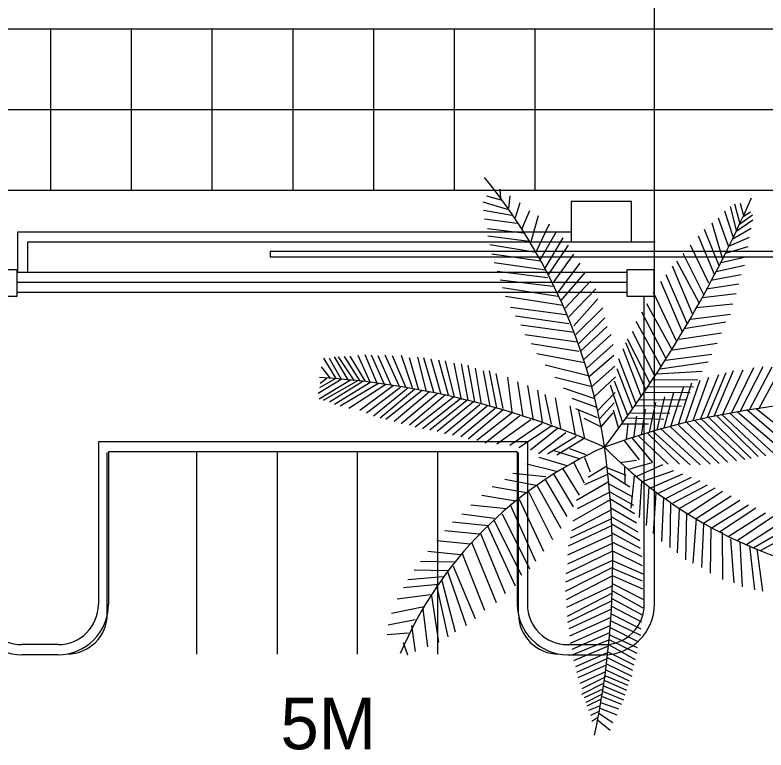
# Model space of a CAD drawing. Extents: x 6711323 to 6714641, y 1869258 to 1871224.
# Drawn here: x 6712869.21 to 6712906.43, y 1869705.35 to 1869741.77 of the extents above; entities that cross this region are included whole.
import ezdxf

# ---------------------------------------------------------------- set-up
doc = ezdxf.new("R2010")
doc.units = 0
for name, color, linetype in [('Curb Gutter (21)', 7, 'Continuous'), ('Exist Veg_Nat(4)', 7, 'Continuous'), ('Front Align (17)', 7, 'Continuous'), ('Misc CnstDet(22)', 7, 'Continuous'), ('Pave Edges (20)', 7, 'Continuous'), ('Ramp Anno (14)', 7, 'Continuous'), ('Undefined (Lv19)', 7, 'Continuous'), ('Undefined (Lv26)', 7, 'Continuous')]:
    doc.layers.add(name, color=color, linetype=linetype)

msp = doc.modelspace()

# ---------------------------------------------------------------- linework, layer by layer
at = {"layer": 'Curb Gutter (21)'}
for p, q in [((6712900.899, 1869712.572), (6712900.899, 1869761.572)), ((6712900.399, 1869712.572), (6712900.399, 1869727.849)), ((6712873.344, 1869720.618), (6712873.344, 1869712.572)), ((6712894.607, 1869720.618), (6712873.344, 1869720.618)), ((6712894.607, 1869720.618), (6712894.607, 1869712.572)), ((6712873.786, 1869712.099), (6712873.786, 1869720.099)), ((6712894.107, 1869720.118), (6712873.844, 1869720.118)), ((6712873.844, 1869720.118), (6712873.844, 1869712.572)), ((6712894.107, 1869720.118), (6712894.107, 1869712.572)), ((6712894.164, 1869712.099), (6712894.164, 1869720.099)), ((6712871.344, 1869710.572), (6712869.552, 1869710.572)), ((6712896.607, 1869710.572), (6712898.399, 1869710.572)), ((6712871.344, 1869710.072), (6712869.552, 1869710.072)), ((6712896.607, 1869710.072), (6712898.399, 1869710.072))]:
    msp.add_line(p, q, dxfattribs=at)
for centre, radius, start, end in [((6712869.552, 1869712.572), 2.5, 180, 270), ((6712869.552, 1869712.572), 2, 180, 270), ((6712871.344, 1869712.572), 2.5, 270, 0), ((6712871.344, 1869712.572), 2, 270, 0), ((6712896.607, 1869712.572), 2.5, 180, 270), ((6712896.607, 1869712.572), 2, 180, 270), ((6712898.399, 1869712.572), 2.5, 270, 360), ((6712898.399, 1869712.572), 2, 270, 360), ((6712871.786, 1869712.099), 2, 270, 0), ((6712896.164, 1869712.099), 2, 180, 270)]:
    msp.add_arc(centre, radius, start, end, dxfattribs=at)
at = {"layer": 'Exist Veg_Nat(4)'}
for p, q in [((6712893.287, 1869732.658), (6712893.263, 1869733.147)), ((6712893.371, 1869732.585), (6712892.598, 1869732.803)), ((6712893.689, 1869732.199), (6712893.753, 1869732.818)), ((6712893.624, 1869732.144), (6712892.418, 1869732.499)), ((6712894.017, 1869731.748), (6712894.244, 1869732.489)), ((6712905.139, 1869731.476), (6712904.89, 1869732.406)), ((6712905.319, 1869731.878), (6712905.165, 1869732.436)), ((6712893.841, 1869731.844), (6712892.424, 1869732.083)), ((6712894.331, 1869731.159), (6712894.727, 1869732.092)), ((6712904.803, 1869730.774), (6712904.391, 1869732.047)), ((6712904.977, 1869731.109), (6712904.665, 1869732.287)), ((6712905.295, 1869731.795), (6712905.659, 1869732.027)), ((6712894.099, 1869731.449), (6712892.48, 1869731.662)), ((6712894.793, 1869730.556), (6712895.151, 1869731.839)), ((6712904.59, 1869730.271), (6712904.084, 1869731.714)), ((6712905.119, 1869731.417), (6712905.76, 1869731.874)), ((6712895.04, 1869730.043), (6712895.708, 1869731.434)), ((6712904.277, 1869729.728), (6712903.763, 1869731.453)), ((6712904.942, 1869731.039), (6712905.774, 1869731.629)), ((6712894.396, 1869730.957), (6712892.63, 1869731.185)), ((6712895.219, 1869729.608), (6712896.043, 1869731.052)), ((6712904.103, 1869729.34), (6712903.388, 1869731.149)), ((6712904.763, 1869730.659), (6712905.694, 1869731.209)), ((6712894.702, 1869730.556), (6712892.641, 1869730.815)), ((6712895.48, 1869729.233), (6712896.385, 1869730.738)), ((6712903.877, 1869728.908), (6712903.081, 1869730.817)), ((6712904.597, 1869730.318), (6712905.608, 1869730.768)), ((6712895.044, 1869730.013), (6712892.746, 1869730.389)), ((6712895.674, 1869728.935), (6712896.646, 1869730.364)), ((6712903.603, 1869728.48), (6712902.686, 1869730.373)), ((6712904.43, 1869729.976), (6712905.542, 1869730.303)), ((6712895.248, 1869729.577), (6712892.847, 1869729.917)), ((6712895.935, 1869728.561), (6712896.9, 1869729.921)), ((6712903.357, 1869727.909), (6712902.319, 1869729.951)), ((6712904.15, 1869729.501), (6712905.496, 1869729.812)), ((6712895.5, 1869729.136), (6712892.952, 1869729.491)), ((6712896.101, 1869727.988), (6712897.228, 1869729.47)), ((6712903.13, 1869727.477), (6712902.005, 1869729.572)), ((6712895.61, 1869728.755), (6712893.106, 1869729.06)), ((6712902.796, 1869726.958), (6712901.804, 1869729.326)), ((6712903.97, 1869729.066), (6712905.363, 1869729.374)), ((6712896.288, 1869727.621), (6712897.482, 1869729.027)), ((6712902.536, 1869726.459), (6712901.484, 1869728.901)), ((6712903.696, 1869728.638), (6712905.204, 1869728.915)), ((6712895.863, 1869728.314), (6712893.26, 1869728.629)), ((6712896.474, 1869727.254), (6712897.735, 1869728.583)), ((6712902.289, 1869726.052), (6712901.223, 1869728.566)), ((6712903.47, 1869728.206), (6712905.091, 1869728.452)), ((6712896.111, 1869727.827), (6712893.37, 1869728.249)), ((6712896.654, 1869726.818), (6712897.996, 1869728.209)), ((6712902.009, 1869725.577), (6712900.863, 1869728.025)), ((6712903.29, 1869727.772), (6712904.951, 1869727.968)), ((6712896.363, 1869727.386), (6712893.525, 1869727.818)), ((6712896.908, 1869726.375), (6712898.095, 1869727.712)), ((6712896.513, 1869726.909), (6712893.768, 1869727.285)), ((6712897.013, 1869725.947), (6712898.348, 1869727.269)), ((6712901.769, 1869725.217), (6712900.523, 1869727.46)), ((6712902.983, 1869727.275), (6712904.785, 1869727.462)), ((6712896.667, 1869726.478), (6712894.02, 1869726.844)), ((6712901.488, 1869724.742), (6712900.276, 1869727.054)), ((6712902.69, 1869726.707), (6712904.666, 1869726.953)), ((6712897.112, 1869725.45), (6712898.447, 1869726.772)), ((6712901.242, 1869724.335), (6712899.995, 1869726.578)), ((6712902.362, 1869726.235), (6712904.446, 1869726.568)), ((6712896.92, 1869726.037), (6712894.273, 1869726.403)), ((6712897.224, 1869725.091), (6712898.553, 1869726.344)), ((6712900.901, 1869723.934), (6712899.809, 1869726.097)), ((6712897.069, 1869725.56), (6712894.472, 1869725.921)), ((6712897.402, 1869724.695), (6712898.764, 1869725.934)), ((6712900.683, 1869723.514), (6712899.57, 1869725.705)), ((6712902.123, 1869725.71), (6712904.226, 1869726.018)), ((6712897.151, 1869725.099), (6712894.793, 1869725.481)), ((6712897.56, 1869724.28), (6712898.857, 1869725.447)), ((6712900.482, 1869723.194), (6712899.484, 1869725.528)), ((6712901.715, 1869725.173), (6712904.013, 1869725.515)), ((6712897.442, 1869724.531), (6712895.079, 1869724.988)), ((6712900.249, 1869722.878), (6712899.353, 1869725.231)), ((6712901.455, 1869724.673), (6712903.746, 1869724.969)), ((6712885.127, 1869723.756), (6712884.516, 1869724.761)), ((6712885.399, 1869723.706), (6712884.792, 1869724.754)), ((6712885.721, 1869723.694), (6712885.054, 1869724.834)), ((6712886.038, 1869723.64), (6712885.239, 1869724.836)), ((6712886.314, 1869723.633), (6712885.54, 1869724.848)), ((6712886.57, 1869723.649), (6712885.818, 1869724.862)), ((6712886.817, 1869723.581), (6712886.215, 1869724.907)), ((6712887.176, 1869723.48), (6712886.565, 1869724.935)), ((6712887.5, 1869723.489), (6712886.886, 1869724.923)), ((6712887.849, 1869723.435), (6712887.217, 1869724.881)), ((6712888.253, 1869723.393), (6712887.555, 1869724.915)), ((6712888.581, 1869723.325), (6712887.923, 1869724.877)), ((6712888.912, 1869723.291), (6712888.372, 1869724.9)), ((6712889.203, 1869723.226), (6712888.77, 1869724.79)), ((6712889.601, 1869723.116), (6712889.182, 1869724.816)), ((6712889.969, 1869723.078), (6712889.476, 1869724.786)), ((6712890.33, 1869722.971), (6712889.841, 1869724.714)), ((6712890.698, 1869722.933), (6712890.209, 1869724.676)), ((6712890.986, 1869722.835), (6712890.54, 1869724.641)), ((6712897.69, 1869723.869), (6712898.887, 1869724.913)), ((6712899.979, 1869722.534), (6712899.134, 1869724.728)), ((6712901.181, 1869724.245), (6712903.573, 1869724.581)), ((6712884.83, 1869723.787), (6712884.404, 1869724.344)), ((6712891.347, 1869722.728), (6712890.975, 1869724.527)), ((6712891.678, 1869722.694), (6712891.343, 1869724.489)), ((6712892.006, 1869722.626), (6712891.671, 1869724.421)), ((6712892.327, 1869722.489), (6712892.028, 1869724.28)), ((6712897.69, 1869723.869), (6712895.48, 1869724.416)), ((6712897.78, 1869723.355), (6712898.947, 1869724.376)), ((6712899.817, 1869722.271), (6712899.05, 1869724.24)), ((6712904.3, 1869721.994), (6712905.297, 1869724.195)), ((6712904.725, 1869722.047), (6712905.832, 1869724.302)), ((6712905.154, 1869722.133), (6712906.292, 1869724.352)), ((6712905.617, 1869722.215), (6712906.745, 1869724.338)), ((6712906.077, 1869722.265), (6712907.24, 1869724.384)), ((6712892.762, 1869722.375), (6712892.423, 1869724.136)), ((6712893.089, 1869722.307), (6712892.721, 1869724.14)), ((6712893.406, 1869722.28), (6712893.064, 1869724.004)), ((6712893.844, 1869722.114), (6712893.631, 1869723.825)), ((6712897.899, 1869722.839), (6712898.978, 1869723.842)), ((6712901.028, 1869723.996), (6712903.273, 1869724.131)), ((6712902.82, 1869721.676), (6712903.594, 1869723.827)), ((6712903.208, 1869721.77), (6712904.102, 1869723.962)), ((6712903.535, 1869721.844), (6712904.461, 1869724.06)), ((6712903.859, 1869721.891), (6712904.819, 1869724.157)), ((6712885.376, 1869723.709), (6712884.243, 1869723.012)), ((6712885.835, 1869723.683), (6712884.283, 1869722.73)), ((6712885.105, 1869723.758), (6712884.296, 1869723.306)), ((6712884.666, 1869723.761), (6712884.341, 1869723.516)), ((6712886.178, 1869723.647), (6712884.484, 1869722.666)), ((6712886.452, 1869723.619), (6712884.799, 1869722.591)), ((6712886.84, 1869723.579), (6712885.041, 1869722.48)), ((6712887.226, 1869723.517), (6712885.332, 1869722.386)), ((6712887.591, 1869723.462), (6712885.757, 1869722.27)), ((6712894.404, 1869721.875), (6712894.127, 1869723.593)), ((6712897.751, 1869723.358), (6712895.962, 1869723.808)), ((6712899.581, 1869721.924), (6712898.92, 1869723.634)), ((6712900.801, 1869723.688), (6712903.047, 1869723.703)), ((6712902.103, 1869721.482), (6712902.751, 1869723.538)), ((6712902.464, 1869721.605), (6712903.173, 1869723.682)), ((6712887.955, 1869723.39), (6712886.305, 1869722.179)), ((6712888.32, 1869723.317), (6712886.626, 1869722.043)), ((6712888.688, 1869723.279), (6712886.983, 1869721.902)), ((6712889.016, 1869723.211), (6712887.307, 1869721.799)), ((6712889.384, 1869723.173), (6712887.598, 1869721.735)), ((6712889.748, 1869723.101), (6712887.996, 1869721.625)), ((6712894.907, 1869721.703), (6712894.629, 1869723.42)), ((6712895.351, 1869721.596), (6712895.125, 1869723.188)), ((6712897.947, 1869722.754), (6712896.395, 1869723.286)), ((6712899.314, 1869721.611), (6712898.732, 1869723.437)), ((6712900.601, 1869723.368), (6712902.843, 1869723.353)), ((6712901.715, 1869721.387), (6712902.355, 1869723.363)), ((6712890.15, 1869723.025), (6712888.357, 1869721.518)), ((6712890.551, 1869722.949), (6712888.759, 1869721.442)), ((6712890.949, 1869722.838), (6712889.046, 1869721.343)), ((6712891.314, 1869722.766), (6712889.411, 1869721.271)), ((6712895.795, 1869721.49), (6712895.492, 1869722.969)), ((6712896.262, 1869721.281), (6712896, 1869722.799)), ((6712898.046, 1869722.319), (6712896.829, 1869722.763)), ((6712898.086, 1869722.156), (6712898.956, 1869723.074)), ((6712900.13, 1869722.704), (6712902.442, 1869722.713)), ((6712900.436, 1869723.075), (6712902.679, 1869723.06)), ((6712901.034, 1869721.205), (6712901.413, 1869722.852)), ((6712901.388, 1869721.313), (6712901.86, 1869723.065)), ((6712891.601, 1869722.668), (6712889.775, 1869721.199)), ((6712891.929, 1869722.599), (6712890.14, 1869721.127)), ((6712892.249, 1869722.462), (6712890.501, 1869721.021)), ((6712892.614, 1869722.39), (6712890.902, 1869720.944)), ((6712896.996, 1869720.946), (6712896.727, 1869722.4)), ((6712898.19, 1869721.773), (6712898.901, 1869722.549)), ((6712899.9, 1869722.418), (6712902.241, 1869722.393)), ((6712900.664, 1869721.104), (6712900.965, 1869722.567)), ((6712893.012, 1869722.28), (6712891.304, 1869720.869)), ((6712893.413, 1869722.204), (6712891.665, 1869720.762)), ((6712893.844, 1869722.056), (6712892.103, 1869720.682)), ((6712898.083, 1869721.805), (6712897.007, 1869722.264)), ((6712897.453, 1869720.781), (6712897.162, 1869722.174)), ((6712898.285, 1869721.376), (6712898.858, 1869722.061)), ((6712899.117, 1869721.322), (6712898.871, 1869722.183)), ((6712899.729, 1869722.064), (6712901.67, 1869722.049)), ((6712900.26, 1869720.953), (6712900.452, 1869722.233)), ((6712904.231, 1869722.001), (6712906.429, 1869719.924)), ((6712904.621, 1869722.058), (6712906.826, 1869720.045)), ((6712905.012, 1869722.115), (6712907.293, 1869720.159)), ((6712905.478, 1869722.229), (6712907.725, 1869720.277)), ((6712905.938, 1869722.279), (6712908.167, 1869720.491)), ((6712894.211, 1869721.895), (6712892.514, 1869720.563)), ((6712894.778, 1869721.716), (6712893.093, 1869720.503)), ((6712898.282, 1869721.346), (6712897.422, 1869721.775)), ((6712899.502, 1869721.808), (6712901.37, 1869721.739)), ((6712899.888, 1869720.825), (6712900.028, 1869721.889)), ((6712902.493, 1869721.603), (6712904.525, 1869719.619)), ((6712902.88, 1869721.697), (6712904.967, 1869719.681)), ((6712903.233, 1869721.741), (6712905.38, 1869719.745)), ((6712903.566, 1869721.868), (6712905.704, 1869719.792)), ((6712903.98, 1869721.933), (6712906.042, 1869719.899)), ((6712895.344, 1869721.537), (6712893.736, 1869720.436)), ((6712895.853, 1869721.424), (6712894.18, 1869720.33)), ((6712896.098, 1869721.278), (6712894.752, 1869720.211)), ((6712899.304, 1869721.519), (6712900.609, 1869721.508)), ((6712899.522, 1869720.752), (6712899.601, 1869721.518)), ((6712901.21, 1869721.278), (6712903.175, 1869719.489)), ((6712901.658, 1869721.393), (6712903.672, 1869719.519)), ((6712902.1, 1869721.455), (6712904.111, 1869719.554)), ((6712896.519, 1869721.06), (6712895.155, 1869720.034)), ((6712897.029, 1869720.887), (6712895.599, 1869720.012)), ((6712900.107, 1869720.913), (6712901.577, 1869719.517)), ((6712900.567, 1869721.032), (6712902.144, 1869719.514)), ((6712900.82, 1869721.157), (6712902.681, 1869719.487)), ((6712897.42, 1869720.784), (6712896.063, 1869719.964)), ((6712899.386, 1869720.71), (6712900.141, 1869719.722)), ((6712899.767, 1869720.841), (6712900.802, 1869719.597)), ((6712897.193, 1869719.773), (6712895.938, 1869720.169)), ((6712897.514, 1869719.979), (6712896.713, 1869720.272)), ((6712896.582, 1869719.436), (6712895.185, 1869719.847)), ((6712897.438, 1869719.852), (6712897.714, 1869719.141)), ((6712896.049, 1869719.158), (6712894.574, 1869719.511)), ((6712896.906, 1869719.583), (6712897.425, 1869718.596)), ((6712898.55, 1869719.418), (6712897.623, 1869718.851)), ((6712899.21, 1869719.594), (6712900.016, 1869719.721)), ((6712899.413, 1869719.364), (6712899.443, 1869718.558)), ((6712899.63, 1869719.272), (6712900.797, 1869719.605)), ((6712900.032, 1869718.914), (6712901.318, 1869719.5)), ((6712895.517, 1869718.88), (6712893.878, 1869719.05)), ((6712895.913, 1869719.003), (6712896.874, 1869717.395)), ((6712896.369, 1869719.28), (6712897.167, 1869717.976)), ((6712898.582, 1869718.996), (6712897.434, 1869718.486)), ((6712898.543, 1869719.349), (6712899.486, 1869718.972)), ((6712898.626, 1869719.061), (6712899.69, 1869718.392)), ((6712900.397, 1869718.697), (6712901.868, 1869719.203)), ((6712900.749, 1869718.361), (6712902.302, 1869719.039)), ((6712895.042, 1869718.463), (6712893.488, 1869718.757)), ((6712895.496, 1869718.723), (6712896.553, 1869716.925)), ((6712898.607, 1869718.631), (6712897.044, 1869717.715)), ((6712899.904, 1869718.927), (6712899.739, 1869717.328)), ((6712900.262, 1869718.651), (6712900.143, 1869716.868)), ((6712901.107, 1869718.085), (6712902.737, 1869718.874)), ((6712901.466, 1869717.808), (6712903.172, 1869718.709)), ((6712894.577, 1869718.099), (6712892.859, 1869718.385)), ((6712895.082, 1869718.479), (6712896.26, 1869716.345)), ((6712898.647, 1869718.534), (6712899.77, 1869717.921)), ((6712900.621, 1869718.374), (6712900.489, 1869716.473)), ((6712901.83, 1869717.591), (6712903.536, 1869718.492)), ((6712902.125, 1869717.321), (6712903.907, 1869718.334)), ((6712894.03, 1869717.689), (6712892.35, 1869717.97)), ((6712894.661, 1869718.163), (6712895.852, 1869715.776)), ((6712898.653, 1869718.117), (6712897.075, 1869717.294)), ((6712898.658, 1869718.163), (6712899.859, 1869717.484)), ((6712900.979, 1869718.098), (6712900.835, 1869716.078)), ((6712901.344, 1869717.881), (6712901.245, 1869715.676)), ((6712902.547, 1869717.038), (6712904.277, 1869718.176)), ((6712902.976, 1869716.814), (6712904.706, 1869717.952)), ((6712894.195, 1869717.78), (6712895.405, 1869715.211)), ((6712898.714, 1869717.741), (6712896.86, 1869716.683)), ((6712898.697, 1869717.812), (6712899.915, 1869717.062)), ((6712901.703, 1869717.604), (6712901.667, 1869715.393)), ((6712903.34, 1869716.597), (6712905.134, 1869717.729)), ((6712903.768, 1869716.373), (6712905.562, 1869717.505)), ((6712893.563, 1869717.306), (6712891.795, 1869717.489)), ((6712893.773, 1869717.464), (6712895.004, 1869714.714)), ((6712898.736, 1869717.23), (6712896.786, 1869716.205)), ((6712898.748, 1869717.344), (6712900.018, 1869716.612)), ((6712902.125, 1869717.321), (6712902.026, 1869715.117)), ((6712904.133, 1869716.156), (6712905.933, 1869717.346)), ((6712892.97, 1869716.829), (6712891.36, 1869717.031)), ((6712894.328, 1869713.994), (6712892.943, 1869716.759)), ((6712894.729, 1869714.311), (6712893.38, 1869717.038)), ((6712898.768, 1869716.81), (6712896.723, 1869715.841)), ((6712898.777, 1869716.902), (6712900.072, 1869716.166)), ((6712902.489, 1869717.104), (6712902.442, 1869714.774)), ((6712902.976, 1869716.814), (6712902.813, 1869714.616)), ((6712904.559, 1869715.925), (6712906.407, 1869717.102)), ((6712905.01, 1869715.733), (6712906.764, 1869716.92)), ((6712892.661, 1869716.465), (6712890.893, 1869716.648)), ((6712892.638, 1869716.432), (6712894.004, 1869713.488)), ((6712898.781, 1869716.462), (6712896.634, 1869715.458)), ((6712898.791, 1869716.553), (6712900.177, 1869715.739)), ((6712903.334, 1869716.538), (6712903.241, 1869714.393)), ((6712903.704, 1869716.38), (6712903.664, 1869714.109)), ((6712905.427, 1869715.515), (6712907.24, 1869716.667)), ((6712905.822, 1869715.387), (6712907.657, 1869716.449)), ((6712892.209, 1869716.045), (6712890.518, 1869716.219)), ((6712892.29, 1869716.073), (6712893.498, 1869713.109)), ((6712898.811, 1869716.019), (6712896.586, 1869715)), ((6712898.795, 1869716.113), (6712900.187, 1869715.345)), ((6712904.261, 1869716.143), (6712904.277, 1869713.807)), ((6712906.151, 1869715.236), (6712908.012, 1869716.238)), ((6712891.77, 1869715.551), (6712890.117, 1869715.722)), ((6712898.822, 1869715.648), (6712900.27, 1869714.943)), ((6712904.677, 1869715.8), (6712904.839, 1869713.629)), ((6712905.128, 1869715.662), (6712905.244, 1869713.438)), ((6712891.854, 1869715.614), (6712893.063, 1869712.651)), ((6712898.815, 1869715.579), (6712896.591, 1869714.56)), ((6712905.61, 1869715.467), (6712905.856, 1869713.287)), ((6712905.971, 1869715.313), (6712906.256, 1869713.217)), ((6712891.289, 1869715.026), (6712889.675, 1869715.193)), ((6712891.373, 1869715.089), (6712892.48, 1869712.281)), ((6712898.827, 1869715.208), (6712896.516, 1869714.082)), ((6712898.851, 1869715.205), (6712900.299, 1869714.5)), ((6712890.979, 1869714.663), (6712889.312, 1869714.692)), ((6712898.829, 1869714.745), (6712896.498, 1869713.667)), ((6712898.829, 1869714.745), (6712900.33, 1869714.081)), ((6712890.662, 1869714.229), (6712888.995, 1869714.257)), ((6712890.639, 1869714.195), (6712891.566, 1869711.513)), ((6712890.919, 1869714.454), (6712892.01, 1869711.862)), ((6712898.818, 1869714.399), (6712896.476, 1869713.207)), ((6712900.317, 1869713.712), (6712898.838, 1869714.351)), ((6712890.437, 1869713.929), (6712888.675, 1869713.787)), ((6712898.825, 1869713.982), (6712896.532, 1869712.785)), ((6712900.326, 1869713.318), (6712898.825, 1869713.982)), ((6712890.185, 1869713.559), (6712888.458, 1869713.379)), ((6712890.101, 1869713.496), (6712890.655, 1869710.96)), ((6712890.361, 1869713.757), (6712891.03, 1869711.209)), ((6712898.797, 1869713.476), (6712896.543, 1869712.413)), ((6712898.834, 1869713.588), (6712900.326, 1869712.832)), ((6712889.809, 1869713.041), (6712888.148, 1869712.82)), ((6712898.811, 1869713.127), (6712896.573, 1869711.971)), ((6712898.823, 1869713.242), (6712900.33, 1869712.392)), ((6712889.856, 1869712.987), (6712890.201, 1869710.695)), ((6712898.796, 1869712.736), (6712896.591, 1869711.668)), ((6712898.783, 1869712.853), (6712900.295, 1869712.049)), ((6712889.482, 1869712.437), (6712887.863, 1869712.114)), ((6712889.42, 1869712.345), (6712889.648, 1869710.458)), ((6712898.778, 1869712.321), (6712896.659, 1869711.36)), ((6712898.769, 1869712.484), (6712900.26, 1869711.705)), ((6712898.754, 1869712.092), (6712900.224, 1869711.362)), ((6712889.046, 1869711.795), (6712887.699, 1869711.542)), ((6712898.735, 1869711.909), (6712896.695, 1869710.986)), ((6712898.743, 1869711.746), (6712900.215, 1869711.039)), ((6712888.859, 1869711.52), (6712889.043, 1869710.226)), ((6712898.719, 1869711.517), (6712896.734, 1869710.635)), ((6712898.71, 1869711.426), (6712900.106, 1869710.703)), ((6712888.714, 1869711.143), (6712887.649, 1869711.057)), ((6712898.682, 1869711.151), (6712896.802, 1869710.327)), ((6712898.671, 1869710.805), (6712900.025, 1869710.156)), ((6712898.672, 1869711.06), (6712900.053, 1869710.431)), ((6712888.455, 1869710.679), (6712888.656, 1869710.07)), ((6712898.619, 1869710.787), (6712896.85, 1869710.068)), ((6712898.613, 1869710.487), (6712896.893, 1869709.763)), ((6712898.622, 1869710.579), (6712899.942, 1869709.841)), ((6712898.555, 1869710.169), (6712896.988, 1869709.476)), ((6712898.585, 1869710.213), (6712899.889, 1869709.569)), ((6712898.549, 1869709.869), (6712897.034, 1869709.193)), ((6712898.556, 1869709.938), (6712899.812, 1869709.299)), ((6712898.516, 1869709.549), (6712897.106, 1869708.931)), ((6712898.493, 1869709.32), (6712899.658, 1869708.783)), ((6712898.523, 1869709.618), (6712899.781, 1869709.002)), ((6712898.483, 1869709.229), (6712897.201, 1869708.644)), ((6712898.455, 1869708.954), (6712897.299, 1869708.379)), ((6712898.439, 1869709.048), (6712899.585, 1869708.559)), ((6712898.399, 1869708.659), (6712897.295, 1869708.102)), ((6712898.438, 1869708.793), (6712899.51, 1869708.312)), ((6712898.344, 1869708.364), (6712897.426, 1869707.927)), ((6712898.334, 1869708.272), (6712899.362, 1869707.842)), ((6712898.385, 1869708.521), (6712899.437, 1869708.089)), ((6712898.318, 1869708.112), (6712897.504, 1869707.71)), ((6712898.267, 1869707.863), (6712897.559, 1869707.519)), ((6712898.306, 1869707.997), (6712899.264, 1869707.621)), ((6712898.209, 1869707.545), (6712897.636, 1869707.303)), ((6712898.226, 1869707.705), (6712899.115, 1869707.382)), ((6712898.181, 1869707.27), (6712897.736, 1869707.062)), ((6712898.169, 1869707.156), (6712898.847, 1869706.715)), ((6712898.198, 1869707.43), (6712899.035, 1869707.089)), ((6712898.099, 1869706.955), (6712897.804, 1869706.754)), ((6712898.087, 1869706.84), (6712898.708, 1869706.337))]:
    msp.add_line(p, q, dxfattribs=at)
for centre, radius, start, end in [((6712870.8, 1869716.07), 27.96, 8.8323, 39.1519), ((6712851.073, 1869756.591), 59.624, 322.58277, 336.39358), ((6712881.672, 1869682.391), 41.505, 66.1888, 86.3559), ((6712911.766, 1869683.309), 39.381, 88.7993, 109.7964), ((6712906.347, 1869702.403), 19.628, 113.7938, 156.8079), ((6712857.931, 1869714.623), 40.903, 347.9585, 8.0664), ((6712914.626, 1869736.331), 22.745, 224.5927, 260.5985)]:
    msp.add_arc(centre, radius, start, end, dxfattribs=at)
at = {"layer": 'Front Align (17)'}
for p, q in [((6712878.219, 1869710.099), (6712878.219, 1869720.099)), ((6712882.219, 1869710.099), (6712882.219, 1869720.099)), ((6712886.192, 1869710.099), (6712886.192, 1869720.099)), ((6712890.164, 1869710.099), (6712890.164, 1869720.099))]:
    msp.add_line(p, q, dxfattribs=at)
at = {"layer": 'Misc CnstDet(22)'}
for p, q in [((6712896.773, 1869732.536), (6712896.773, 1869730.536)), ((6712899.773, 1869732.536), (6712896.773, 1869732.536)), ((6712899.773, 1869730.536), (6712899.773, 1869732.536)), ((6712869.351, 1869729.036), (6712869.351, 1869731.036)), ((6712869.351, 1869731.036), (6712896.773, 1869731.036)), ((6712869.851, 1869730.536), (6712900.936, 1869730.536)), ((6712869.851, 1869729.036), (6712869.851, 1869730.536)), ((6712896.773, 1869730.536), (6712899.773, 1869730.536)), ((6712869.296, 1869728.536), (6712899.55, 1869728.536))]:
    msp.add_line(p, q, dxfattribs=at)
msp.add_lwpolyline([(6712881.857, 1869729.798), (6712913.857, 1869729.798), (6712913.857, 1869730.048), (6712881.857, 1869730.048)], close=True, dxfattribs=at)
at = {"layer": 'Pave Edges (20)'}
for p, q in [((6712874.974, 1869741.072), (6712874.974, 1869733.072)), ((6712882.974, 1869741.072), (6712882.974, 1869733.072)), ((6712890.974, 1869741.072), (6712890.974, 1869733.072)), ((6712939.639, 1869737.072), (6712560.557, 1869737.072))]:
    msp.add_line(p, q, dxfattribs=at)
at = {"layer": 'Undefined (Lv19)'}
for p, q in [((6712951.646, 1869741.072), (6712671.076, 1869741.072)), ((6712870.974, 1869741.072), (6712870.974, 1869733.072)), ((6712878.974, 1869741.072), (6712878.974, 1869733.072)), ((6712886.974, 1869741.072), (6712886.974, 1869733.072)), ((6712894.974, 1869741.072), (6712894.974, 1869733.072)), ((6712900.899, 1869733.072), (6712900.899, 1869741.079)), ((6712951.556, 1869733.072), (6712672.694, 1869733.072))]:
    msp.add_line(p, q, dxfattribs=at)
at = {"layer": 'Undefined (Lv26)'}
for p, q in [((6712867.962, 1869729.158), (6712869.296, 1869729.158)), ((6712869.296, 1869729.158), (6712869.296, 1869727.825)), ((6712869.296, 1869729.036), (6712899.559, 1869729.036)), ((6712899.543, 1869727.825), (6712899.543, 1869729.158)), ((6712899.543, 1869729.158), (6712900.876, 1869729.158)), ((6712900.876, 1869729.158), (6712900.876, 1869727.825)), ((6712869.296, 1869728.036), (6712899.559, 1869728.036)), ((6712869.296, 1869727.825), (6712867.962, 1869727.825)), ((6712900.876, 1869727.825), (6712899.543, 1869727.825))]:
    msp.add_line(p, q, dxfattribs=at)

# ---------------------------------------------------------------- texts
at = {"layer": 'Ramp Anno (14)'}
msp.add_text('5M', height=2.55, dxfattribs=at).set_placement((6712882.369, 1869705.386))

doc.saveas('drawing.dxf')
